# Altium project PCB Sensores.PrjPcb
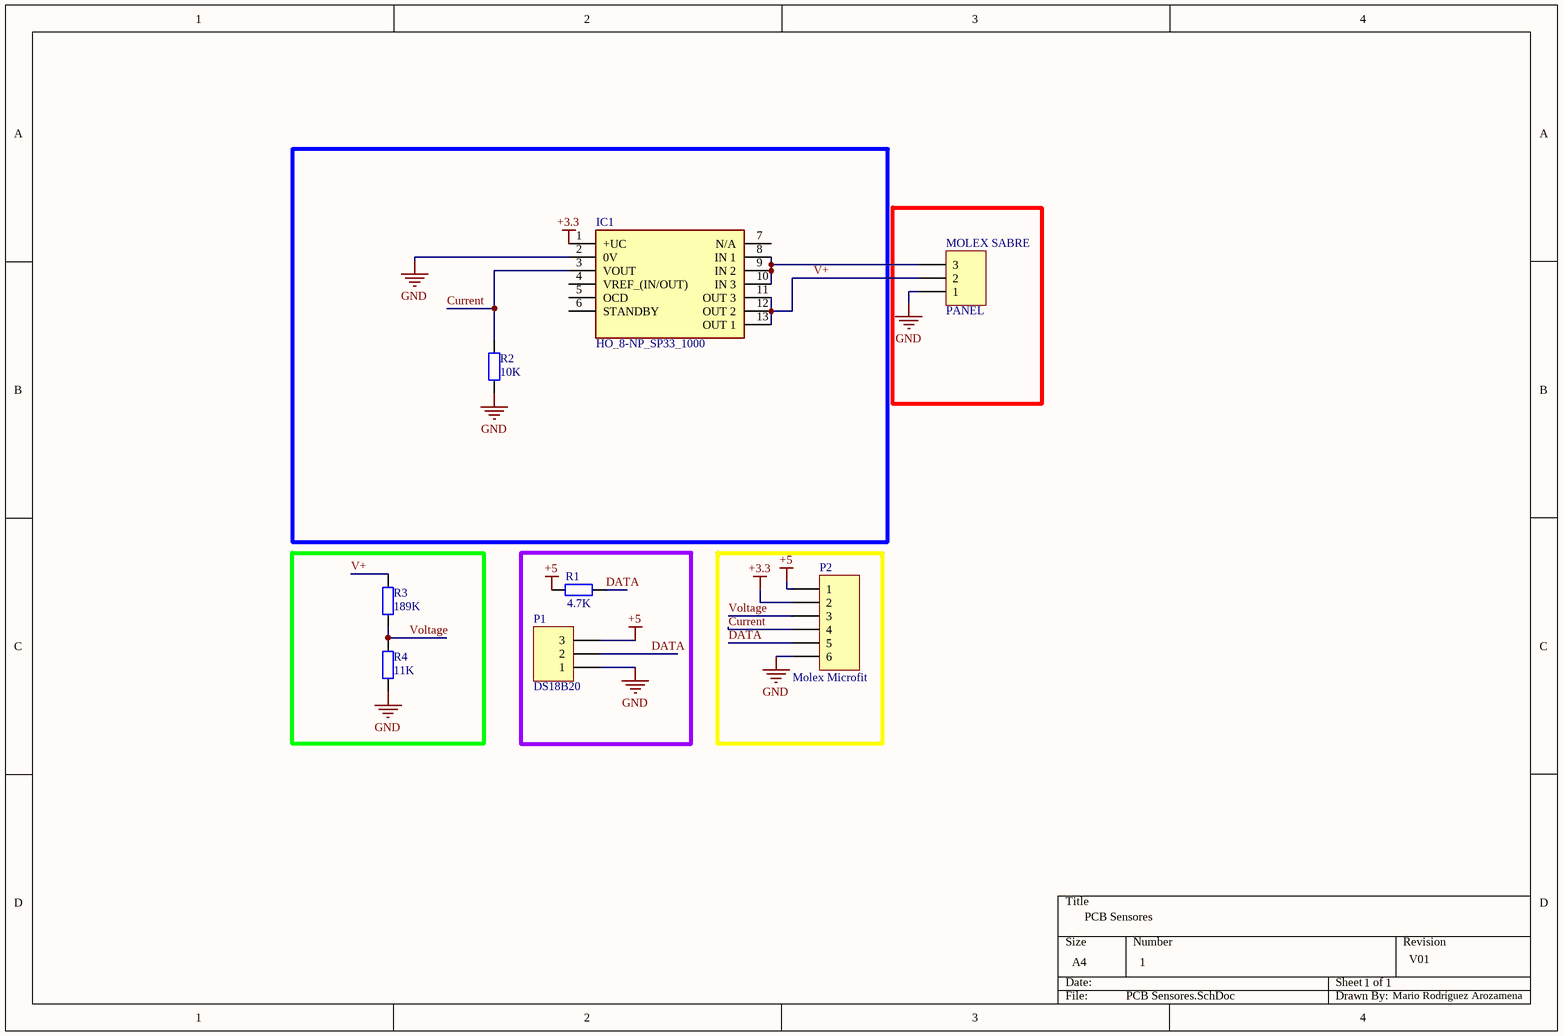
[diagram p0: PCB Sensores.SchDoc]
1 sheet, 8 parts. Net scope: global (net labels, ports and power ports of the same name join across sheets).
Board file: PCB Sensores.PcbDoc

## Sheet PCB Sensores.SchDoc
size A4

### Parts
IC1  HO_8-NP_SP33_1000  [HO8NPSP33-1000]
MOLEX_SABRE  PANEL  [43160-4303]
P1  DS18B20  [43650-0315]
P2  Molex Microfit  [43650-0615]
R1  value 4.7K  [6-0805_M]  (hidden comment: Res2)
R2  value 10K  [6-0805_M]  (hidden comment: Res2)
R3  value 189K  [6-0805_M]  (hidden comment: Res2)
R4  value 11K  [6-0805_M]  (hidden comment: Res2)

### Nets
+3.3: IC1.1(+UC) P2.2
+5: P1.3 P2.1 R1.1
GND: IC1.2(0V) MOLEX_SABRE.1 P1.1 P2.6 R2.1 R4.1
Current: IC1.3(VOUT) P2.4 R2.2
DATA: P1.2 P2.5 R1.2
V+: IC1.11(OUT_3) IC1.12(OUT_2) IC1.13(OUT_1) MOLEX_SABRE.2 R3.2
Voltage: P2.3 R3.1 R4.2
NetIC1_8: IC1.8(IN_1) IC1.9(IN_2) IC1.10(IN_3) MOLEX_SABRE.3

Not connected (* = marked no-connect by the designer): IC1 4(VREF_(IN/OUT)) 5(OCD) 6(STANDBY) 7(N/A)

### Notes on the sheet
- PCB Sensores
- 1
- V01
- Mario Rodríguez Arozamena

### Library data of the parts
IC1 = HO_8-NP_SP33_1000: Integrated Circuit; Manufacturer_Name: LEM; Manufacturer_Part_Number: HO 10-P/SP33
MOLEX_SABRE = Molex SABRE 3pin vertical: Molex SABRE 3pin vertical connector
P1 = Header 3: Header, 3-Pin
P2 = Header 6: Header, 6-Pin
R1-R4 = Res2: Resistor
